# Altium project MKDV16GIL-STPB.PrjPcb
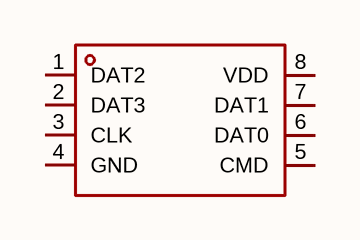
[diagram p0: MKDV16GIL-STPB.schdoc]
1 sheet, 1 parts. Net scope: global (net labels, ports and power ports of the same name join across sheets).

## Sheet MKDV16GIL-STPB.schdoc
size 127 x 101 mm

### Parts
U?  mkdv16gil-stpb  [LGA-8_L8.0-W6.0-P1.27-TL_MKDV4GCL-ABF]  (value not drawn)

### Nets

Not connected (* = marked no-connect by the designer): U? 1(DAT2) 2(DAT3) 3(CLK) 4(GND) 5(CMD) 6(DAT0) 7(DAT1) 8(VDD)

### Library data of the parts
U? = mkdv16gil-stpb: 存储容量:16Gbit;时钟频率(fc):50MHz;工作电压:2.7V~3.6V;; Manufacturer: MK(米客方德); AddInBom: yes; ModelId: ef50f8f4e0d745e797621e4f42c5cff2; ModelTransform: 314.96,236.22,0,0,0,0,0,0,0; Memory Size: 16Gbit; Interface: SPI; Clock Frequency: 50MHz; Standby Supply Current: 250uA; Program / Erase Cycles: 3万次; ECC: 有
